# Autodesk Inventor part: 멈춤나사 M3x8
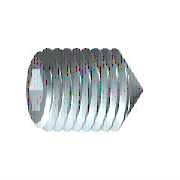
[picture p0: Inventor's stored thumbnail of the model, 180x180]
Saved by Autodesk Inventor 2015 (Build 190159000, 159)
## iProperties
IsCustomPart: 1
Created: 2012-02
Part Number: 멈춤나사 M3x8
Material: 강철, 연강
Description: 6각 소켓 머리 없는 멈춤 나사
Document SubType Name: Modeling
Standard: KS B 1028
Designer: test
Standards Organization: KS
Language: ko-KR
Size Designation: 원추점 M3x8
Categories: <MemberInstance><Categories><Category DisplayName="조임쇠" InternalName="e4da775c-781d-43d5-af7c-5136215cf5a6" Mnemonic="FSTN"><Category DisplayName="볼트" InternalN
Density: 1 g/cm^3
Appearance: 강철
Author: test
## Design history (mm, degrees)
sketch "스케치1"
  geometry: L1 (0, 0)-(5.5, 0); L2 (8, 0.866)-(8, 1.5); L3 (8, 1.5)-(0, 1.5); L4 (8, 0.866)-(6, 0.866); L5 (6, 0.866)-(5.5, 0); L6 (0, -0.3)-(0, 1.8) reference; L7 (0, 1.5)-(0, 0)
  constraints: 13 end point, 3 parallel, 1 collinear, 1 perpendicular, 1 point on line
  dimensions: "d0" = 2 distance of L2.start L4.end (= INTI); "d1" = 60 deg angle of L5 L1; "d2" = 3 diameter of L3 L1 (= NND); "d3" = 1.73205 diameter of L4 L1 (= 1.1547 x SW); "d5" = 8 distance from line of L2 L3.end (= NLG)
revolve "본체" sketch "스케치1" stored, may be unused: angle "d6" = 90 deg
sketch "스케치2"
  geometry: L1 (-0.433, 0.75)-(0.433, 0.75); L2 (0.433, 0.75)-(0.866, 0); L3 (0.866, 0)-(0.433, -0.75); L4 (0.433, -0.75)-(-0.433, -0.75); L5 (-0.433, -0.75)-(-0.866, 0); L6 (-0.866, 0)-(-0.433, 0.75); 3 further points
  constraints: 12 end point, 1 coincident, 1 horizontal, 13 other
extrude "슬롯" join sketch "스케치2" taper "d7" = 0 deg; stored distance "d21" = 10
workaxis "Work Axis1"
workplane "Work Plane1"
sketch "스케치4"
  geometry: L1 (0, 0.15)-(-1.35, 1.5) reference; L2 (0, -0.15)-(-1.35, -1.5) reference; L3 (-1.35, -1.5)-(0.15, 0); L4 (-1.35, 1.5)-(0.15, 0); 2 further points
  constraints: 4 end point, 1 coincident, 1 collinear, 1 horizontal alignment
body "Solid1"
feature "스레드" dims "d12" = 8 (= NLG), "d13" = 0
chamfer "모따기1" distance "d8" = 1.35 (computed from NND, SPD, FAWI); stored, may be unused: angle "d9" = 45 deg (= FAWI), second distance "d34" = 1.35 (computed from NND, SPD, FAWI)
chamfer "모따기2" distance "d10" = 0.30673 (= -0.5 x GD1 + 0.5 x NND); stored, may be unused: angle "d11" = 45 deg (= FAWI), second distance "d35" = 0.30673 (= -0.5 x GD1 + 0.5 x NND)
other parameters: "NND" = 3 [user parameter; used in 5 equation terms], "NLG" = 8 [user parameter; used in 2 equation terms], "INTI" = 2 [user parameter; used in 1 equation term], "FAWI" = 45 deg [user parameter; used in 4 equation terms], "SW" = 1.5 [user parameter; used in 2 equation terms], "GD1" = 2.38655 (= THREADDIA - 1.2269 x PTC) [user parameter; used in 2 equation terms], "d4" = 0, "FAWI1" = 45 deg [user parameter], "SPD" = 0.3 [user parameter; used in 2 equation terms], "d36" = 0, "d37" = 0, "GUL" = 0.30673 (= 0.61345 x PTC) [user parameter], "TOA" = 30 deg [user parameter], "THREADDIA" = 3 [user parameter; used in 1 equation term], "PTC" = 0.5 [user parameter; used in 4 equation terms], "GAL" = 0.30673 (= 0.61345 x PTC) [user parameter], "E0" = 1.7325 (= 1.155 x SW) [user parameter]
